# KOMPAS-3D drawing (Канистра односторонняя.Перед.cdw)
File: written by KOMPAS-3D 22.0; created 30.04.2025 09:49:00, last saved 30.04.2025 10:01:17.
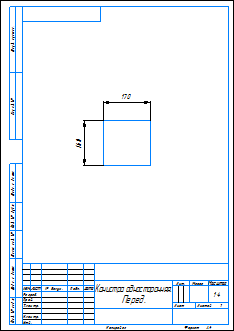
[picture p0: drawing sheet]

Sheet 1: A4, portrait

Document properties: Автор: Admin; Наименование: Канистра односторонняя. Перед; Полное имя файла: D:\28.11.2016\3D модели\Абилимпикс\2025\Канистра односторонняя\Канистра односторонняя.Перед.cdw

Title block, sheet 1: Наименование: Канистра односторонняя. / Перед.; scale: 1:4; Количество листов документа: 1; Форматы листов документа: A4; stored path: D:\28.11.2016\3D модели\Абилимпикс\2025\Канистра односторонняя\Канистра односторонняя.Зад.cdw

Dimensions and other numbers on the sheet: 160; 170; 1:4; 1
